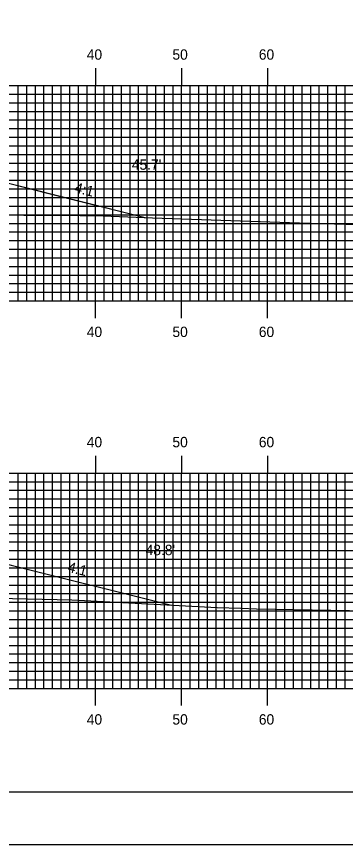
# Model space of a CAD drawing. Extents: x 1772809 to 1773153, y 442591 to 442811.
# Drawn here: x 1773005.9 to 1773044.2, y 442590.5 to 442686.7 of the extents above; entities that cross this region are included whole.
import ezdxf

# ---------------------------------------------------------------- set-up
doc = ezdxf.new("R2010")
doc.units = 0
for name, color, linetype in [('ANNOTATION', 7, 'Continuous'), ('BORDER', 7, 'Continuous'), ('D_Roadway_Centerline', 7, 'Continuous'), ('D_Roadway_SlopeLines', 7, 'Continuous'), ('D_Text_Standard', 7, 'Continuous'), ('H_V ANNOTATION', 7, 'Continuous'), ('MAJOR', 7, 'Continuous'), ('MINOR', 7, 'Continuous'), ('PLOT BOUNDARY', 7, 'Continuous'), ('S_Roadway_Centerline', 7, 'Continuous')]:
    doc.layers.add(name, color=color, linetype=linetype)

msp = doc.modelspace()

# ---------------------------------------------------------------- linework, layer by layer
at = {"layer": 'BORDER'}
msp.add_lwpolyline([(1772825.52, 442596.665), (1773145.52, 442596.665), (1773145.52, 442806.665), (1772825.52, 442806.665)], close=True, dxfattribs=at)
at = {"layer": 'D_Roadway_Centerline'}
for points in [[(1772938.572, 442665.647), (1772943.119, 442666.784), (1772943.663, 442666.92), (1772944.946, 442667.24), (1772955.12, 442669.784), (1772957.831, 442669.893), (1772963.119, 442670.104), (1772973.69, 442670.316), (1772975.12, 442670.344), (1772987.119, 442670.104), (1772991.874, 442669.914), (1772995.12, 442669.784), (1773005.294, 442667.24), (1773009.361, 442666.224), (1773020.862, 442663.348)], [(1772938.304, 442621.329), (1772943.12, 442622.534), (1772944.93, 442622.986), (1772944.946, 442622.99), (1772945.075, 442623.022), (1772955.12, 442625.534), (1772963.12, 442625.854), (1772975.12, 442626.094), (1772980.946, 442625.978), (1772987.12, 442625.854), (1772995.119, 442625.534), (1773000.632, 442624.156), (1773005.293, 442622.99), (1773023.945, 442618.327)]]:
    msp.add_lwpolyline(points, dxfattribs=at)
at = {"layer": 'D_Roadway_SlopeLines'}
for points in [[(1772995.12, 442669.784), (1773005.294, 442667.24), (1773020.862, 442663.348)], [(1772995.119, 442625.534), (1773005.293, 442622.99), (1773023.945, 442618.327)]]:
    msp.add_lwpolyline(points, dxfattribs=at)
at = {"layer": 'MAJOR'}
for p, q in [((1773015.12, 442680.669), (1773015.12, 442678.665)), ((1773025.12, 442680.669), (1773025.12, 442678.665)), ((1773035.12, 442680.669), (1773035.12, 442678.665)), ((1772835.12, 442678.665), (1773115.12, 442678.665)), ((1772835.12, 442678.665), (1773115.12, 442678.665)), ((1773015.12, 442653.665), (1773015.12, 442678.665)), ((1773025.12, 442653.665), (1773025.12, 442678.665)), ((1773035.12, 442653.665), (1773035.12, 442678.665)), ((1772835.12, 442673.665), (1773115.12, 442673.665)), ((1772835.12, 442668.665), (1773115.12, 442668.665)), ((1772835.12, 442663.665), (1773115.12, 442663.665)), ((1772835.12, 442658.665), (1773115.12, 442658.665)), ((1772835.12, 442653.665), (1773115.12, 442653.665)), ((1772835.12, 442653.665), (1773115.12, 442653.665)), ((1773015.12, 442651.661), (1773015.12, 442653.665)), ((1773025.12, 442651.661), (1773025.12, 442653.665)), ((1773035.12, 442651.661), (1773035.12, 442653.665)), ((1773015.12, 442635.669), (1773015.12, 442633.665)), ((1773025.12, 442635.669), (1773025.12, 442633.665)), ((1773035.12, 442635.669), (1773035.12, 442633.665)), ((1772835.12, 442633.665), (1773115.12, 442633.665)), ((1772835.12, 442633.665), (1773115.12, 442633.665)), ((1773015.12, 442608.665), (1773015.12, 442633.665)), ((1773025.12, 442608.665), (1773025.12, 442633.665)), ((1773035.12, 442608.665), (1773035.12, 442633.665)), ((1772835.12, 442628.665), (1773115.12, 442628.665)), ((1772835.12, 442623.665), (1773115.12, 442623.665)), ((1772835.12, 442618.665), (1773115.12, 442618.665)), ((1772835.12, 442613.665), (1773115.12, 442613.665)), ((1772835.12, 442608.665), (1773115.12, 442608.665)), ((1772835.12, 442608.665), (1773115.12, 442608.665)), ((1773015.12, 442606.661), (1773015.12, 442608.665)), ((1773025.12, 442606.661), (1773025.12, 442608.665)), ((1773035.12, 442606.661), (1773035.12, 442608.665))]:
    msp.add_line(p, q, dxfattribs=at)
at = {"layer": 'MINOR'}
for p, q in [((1773006.12, 442653.665), (1773006.12, 442678.665)), ((1773007.12, 442653.665), (1773007.12, 442678.665)), ((1773008.12, 442653.665), (1773008.12, 442678.665)), ((1773009.12, 442653.665), (1773009.12, 442678.665)), ((1773010.12, 442653.665), (1773010.12, 442678.665)), ((1773011.12, 442653.665), (1773011.12, 442678.665)), ((1773012.12, 442653.665), (1773012.12, 442678.665)), ((1773013.12, 442653.665), (1773013.12, 442678.665)), ((1773014.12, 442653.665), (1773014.12, 442678.665)), ((1773016.12, 442653.665), (1773016.12, 442678.665)), ((1773017.12, 442653.665), (1773017.12, 442678.665)), ((1773018.12, 442653.665), (1773018.12, 442678.665)), ((1773019.12, 442653.665), (1773019.12, 442678.665)), ((1773020.12, 442653.665), (1773020.12, 442678.665)), ((1773021.12, 442653.665), (1773021.12, 442678.665)), ((1773022.12, 442653.665), (1773022.12, 442678.665)), ((1773023.12, 442653.665), (1773023.12, 442678.665)), ((1773024.12, 442653.665), (1773024.12, 442678.665)), ((1773026.12, 442653.665), (1773026.12, 442678.665)), ((1773027.12, 442653.665), (1773027.12, 442678.665)), ((1773028.12, 442653.665), (1773028.12, 442678.665)), ((1773029.12, 442653.665), (1773029.12, 442678.665)), ((1773030.12, 442653.665), (1773030.12, 442678.665)), ((1773031.12, 442653.665), (1773031.12, 442678.665)), ((1773032.12, 442653.665), (1773032.12, 442678.665)), ((1773033.12, 442653.665), (1773033.12, 442678.665)), ((1773034.12, 442653.665), (1773034.12, 442678.665)), ((1773036.12, 442653.665), (1773036.12, 442678.665)), ((1773037.12, 442653.665), (1773037.12, 442678.665)), ((1773038.12, 442653.665), (1773038.12, 442678.665)), ((1773039.12, 442653.665), (1773039.12, 442678.665)), ((1773040.12, 442653.665), (1773040.12, 442678.665)), ((1773041.12, 442653.665), (1773041.12, 442678.665)), ((1773042.12, 442653.665), (1773042.12, 442678.665)), ((1773043.12, 442653.665), (1773043.12, 442678.665)), ((1773044.12, 442653.665), (1773044.12, 442678.665)), ((1772835.12, 442677.665), (1773115.12, 442677.665)), ((1772835.12, 442676.665), (1773115.12, 442676.665)), ((1772835.12, 442675.665), (1773115.12, 442675.665)), ((1772835.12, 442674.665), (1773115.12, 442674.665)), ((1772835.12, 442672.665), (1773115.12, 442672.665)), ((1772835.12, 442671.665), (1773115.12, 442671.665)), ((1772835.12, 442670.665), (1773115.12, 442670.665)), ((1772835.12, 442669.665), (1773115.12, 442669.665)), ((1772835.12, 442667.665), (1773115.12, 442667.665)), ((1772835.12, 442666.665), (1773115.12, 442666.665)), ((1772835.12, 442665.665), (1773115.12, 442665.665)), ((1772835.12, 442664.665), (1773115.12, 442664.665)), ((1772835.12, 442662.665), (1773115.12, 442662.665)), ((1772835.12, 442661.665), (1773115.12, 442661.665)), ((1772835.12, 442660.665), (1773115.12, 442660.665)), ((1772835.12, 442659.665), (1773115.12, 442659.665)), ((1772835.12, 442657.665), (1773115.12, 442657.665)), ((1772835.12, 442656.665), (1773115.12, 442656.665)), ((1772835.12, 442655.665), (1773115.12, 442655.665)), ((1772835.12, 442654.665), (1773115.12, 442654.665)), ((1773006.12, 442608.665), (1773006.12, 442633.665)), ((1773007.12, 442608.665), (1773007.12, 442633.665)), ((1773008.12, 442608.665), (1773008.12, 442633.665)), ((1773009.12, 442608.665), (1773009.12, 442633.665)), ((1773010.12, 442608.665), (1773010.12, 442633.665)), ((1773011.12, 442608.665), (1773011.12, 442633.665)), ((1773012.12, 442608.665), (1773012.12, 442633.665)), ((1773013.12, 442608.665), (1773013.12, 442633.665)), ((1773014.12, 442608.665), (1773014.12, 442633.665)), ((1773016.12, 442608.665), (1773016.12, 442633.665)), ((1773017.12, 442608.665), (1773017.12, 442633.665)), ((1773018.12, 442608.665), (1773018.12, 442633.665)), ((1773019.12, 442608.665), (1773019.12, 442633.665)), ((1773020.12, 442608.665), (1773020.12, 442633.665)), ((1773021.12, 442608.665), (1773021.12, 442633.665)), ((1773022.12, 442608.665), (1773022.12, 442633.665)), ((1773023.12, 442608.665), (1773023.12, 442633.665)), ((1773024.12, 442608.665), (1773024.12, 442633.665)), ((1773026.12, 442608.665), (1773026.12, 442633.665)), ((1773027.12, 442608.665), (1773027.12, 442633.665)), ((1773028.12, 442608.665), (1773028.12, 442633.665)), ((1773029.12, 442608.665), (1773029.12, 442633.665)), ((1773030.12, 442608.665), (1773030.12, 442633.665)), ((1773031.12, 442608.665), (1773031.12, 442633.665)), ((1773032.12, 442608.665), (1773032.12, 442633.665)), ((1773033.12, 442608.665), (1773033.12, 442633.665)), ((1773034.12, 442608.665), (1773034.12, 442633.665)), ((1773036.12, 442608.665), (1773036.12, 442633.665)), ((1773037.12, 442608.665), (1773037.12, 442633.665)), ((1773038.12, 442608.665), (1773038.12, 442633.665)), ((1773039.12, 442608.665), (1773039.12, 442633.665)), ((1773040.12, 442608.665), (1773040.12, 442633.665)), ((1773041.12, 442608.665), (1773041.12, 442633.665)), ((1773042.12, 442608.665), (1773042.12, 442633.665)), ((1773043.12, 442608.665), (1773043.12, 442633.665)), ((1773044.12, 442608.665), (1773044.12, 442633.665)), ((1772835.12, 442632.665), (1773115.12, 442632.665)), ((1772835.12, 442631.665), (1773115.12, 442631.665)), ((1772835.12, 442630.665), (1773115.12, 442630.665)), ((1772835.12, 442629.665), (1773115.12, 442629.665)), ((1772835.12, 442627.665), (1773115.12, 442627.665)), ((1772835.12, 442626.665), (1773115.12, 442626.665)), ((1772835.12, 442625.665), (1773115.12, 442625.665)), ((1772835.12, 442624.665), (1773115.12, 442624.665)), ((1772835.12, 442622.665), (1773115.12, 442622.665)), ((1772835.12, 442621.665), (1773115.12, 442621.665)), ((1772835.12, 442620.665), (1773115.12, 442620.665)), ((1772835.12, 442619.665), (1773115.12, 442619.665)), ((1772835.12, 442617.665), (1773115.12, 442617.665)), ((1772835.12, 442616.665), (1773115.12, 442616.665)), ((1772835.12, 442615.665), (1773115.12, 442615.665)), ((1772835.12, 442614.665), (1773115.12, 442614.665)), ((1772835.12, 442612.665), (1773115.12, 442612.665)), ((1772835.12, 442611.665), (1773115.12, 442611.665)), ((1772835.12, 442610.665), (1773115.12, 442610.665)), ((1772835.12, 442609.665), (1773115.12, 442609.665))]:
    msp.add_line(p, q, dxfattribs=at)
at = {"layer": 'PLOT BOUNDARY'}
msp.add_lwpolyline([(1772809.333, 442590.547), (1773149.333, 442590.547), (1773149.333, 442810.547), (1772809.333, 442810.547)], close=True, dxfattribs=at)
at = {"layer": 'S_Roadway_Centerline'}
for points in [[(1772935.479, 442665.743), (1772951.585, 442665.243), (1772955.937, 442665.302), (1772961.706, 442664.916), (1772972.546, 442664.462), (1772987.185, 442663.999), (1772993.671, 442663.693), (1773013.311, 442663.562), (1773014.292, 442663.564), (1773015.021, 442663.567), (1773021.733, 442663.315), (1773035.371, 442662.832), (1773038.833, 442662.712), (1773048.314, 442662.47), (1773056.216, 442662.376), (1773064.83, 442662.134), (1773071.035, 442661.858), (1773090.084, 442661.486), (1773094.75, 442661.414), (1773098.702, 442661.369), (1773107.812, 442661.006), (1773115.12, 442660.898)], [(1772927.491, 442622.198), (1772938.723, 442621.296), (1772949.251, 442621.157), (1772952.79, 442621.064), (1772970.673, 442620.42), (1772976.166, 442620.275), (1772984.607, 442619.852), (1772991.062, 442619.506), (1772997.141, 442619.072), (1773003.711, 442619.13), (1773012.346, 442618.962), (1773019.706, 442618.544), (1773029.253, 442618.057), (1773032.005, 442617.966), (1773033.837, 442617.907), (1773044.639, 442617.715)]]:
    msp.add_lwpolyline(points, dxfattribs=at)

# ---------------------------------------------------------------- texts
at = {"layer": 'ANNOTATION'}
for rotation, p in [(345.96414, (1773012.584, 442666.279)), (345.9629, (1773011.794, 442622.227))]:
    msp.add_text('4:1', height=1.2, rotation=rotation, dxfattribs=at).set_placement(p)
at = {"layer": 'D_Text_Standard'}
for s, p in [("45.7'", (1773019.329, 442668.884)), ("48.8'", (1773020.937, 442624.138))]:
    msp.add_text(s, height=1.2, dxfattribs=at).set_placement(p)
at = {"layer": 'H_V ANNOTATION'}
for s, p in [('40', (1773014.092, 442681.665)), ('50', (1773024.049, 442681.665)), ('60', (1773034.092, 442681.665)), ('40', (1773014.092, 442649.465)), ('50', (1773024.049, 442649.465)), ('60', (1773034.092, 442649.465)), ('40', (1773014.092, 442636.665)), ('50', (1773024.049, 442636.665)), ('60', (1773034.092, 442636.665)), ('40', (1773014.092, 442604.465)), ('50', (1773024.049, 442604.465)), ('60', (1773034.092, 442604.465))]:
    msp.add_text(s, height=1.2, dxfattribs=at).set_placement(p)

doc.saveas('drawing.dxf')
